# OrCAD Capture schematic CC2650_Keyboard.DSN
size A3; title: CC2650_Keyboard_Module; rev: 2.0.0
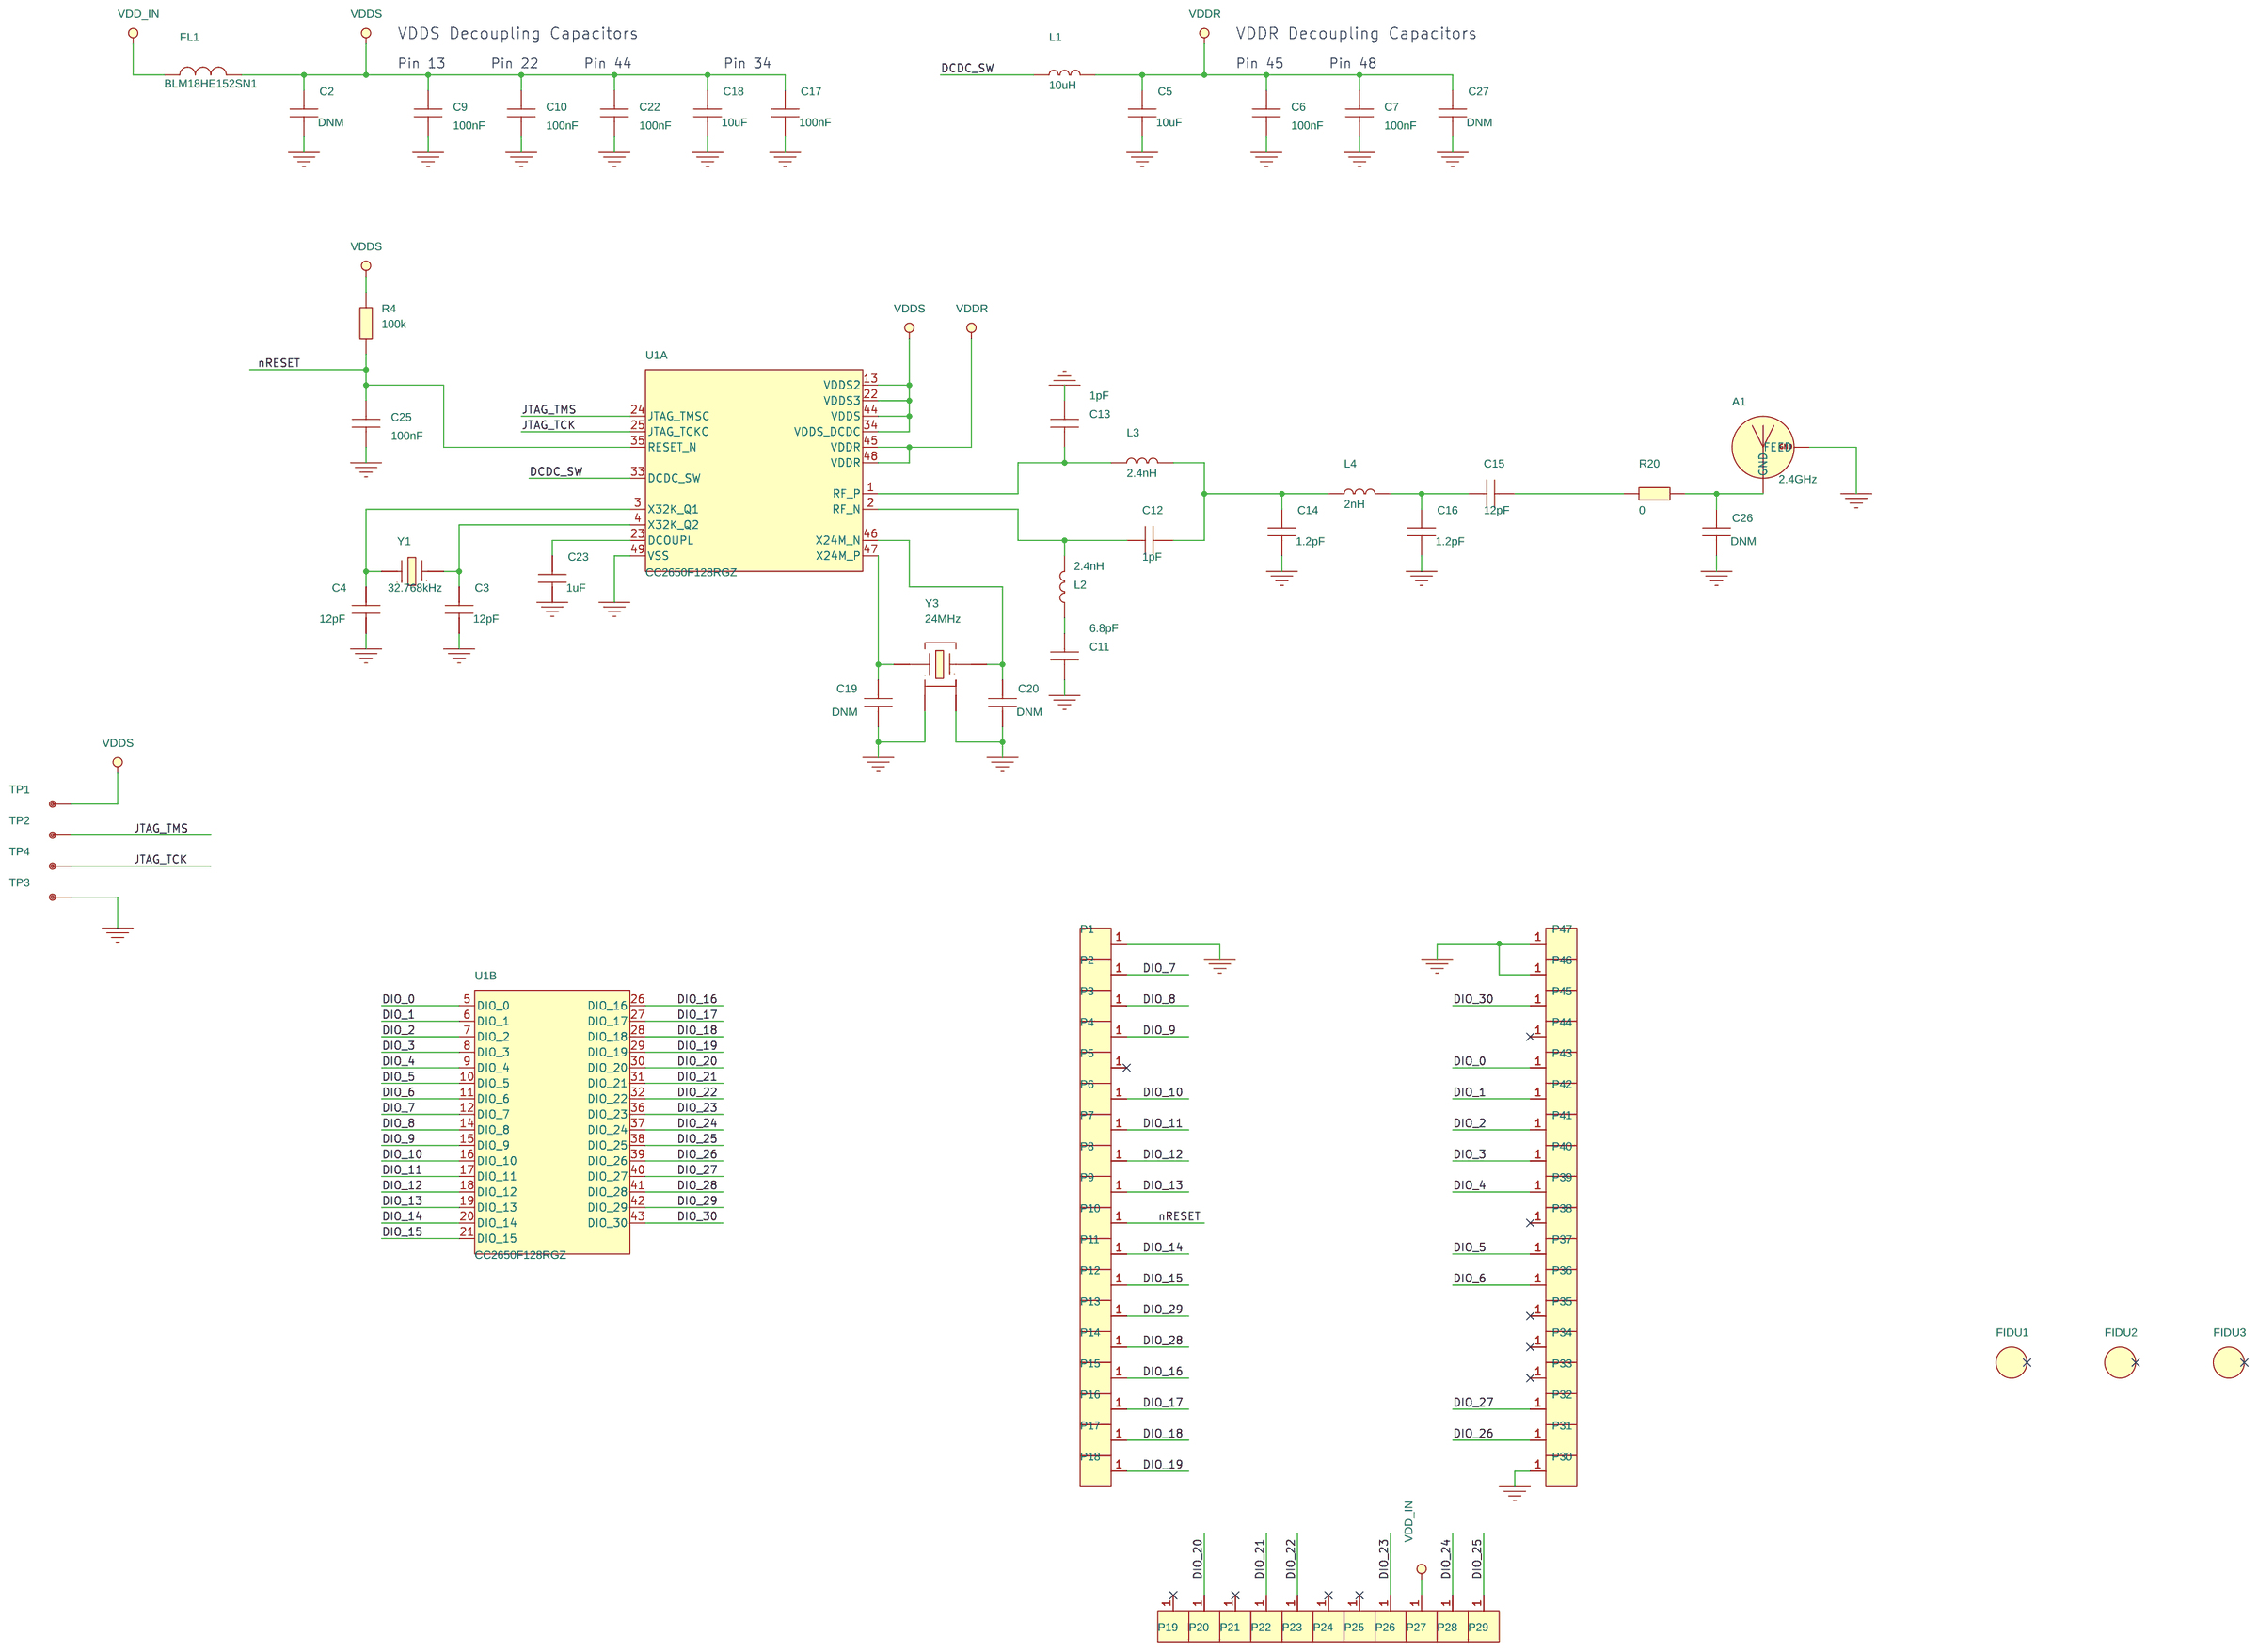
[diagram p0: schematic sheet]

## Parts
A1  2.4GHz  [ANTENNA_MIRROR_AN043CN]
C2  DNM  [CAPC1608X90L]
C3  12pF  [CAPC1005X60L]
C4  12pF  [CAPC1005X60L]
C5  10uF  [CAPC1608X90N]
C6  100nF  [CAPC1005X60L]
C7  100nF  [CAPC1005X60L]
C9  100nF  [CAPC1005X60L]
C10  100nF  [CAPC1005X60L]
C11  6.8pF  [CAPC1005X60L]
C12  1pF  [CAPC1005X60L]
C13  1pF  [CAPC1005X60L]
C14  1.2pF  [CAPC1005X60L]
C15  12pF  [CAPC1005X60L]
C16  1.2pF  [CAPC1005X60L]
C17  100nF  [CAPC1608X90L]
C18  10uF  [CAPC1608X90N]
C19  DNM  [CAPC1005X60L]
C20  DNM  [CAPC1005X60L]
C22  100nF  [CAPC1005X60L]
C23  1uF  [CAPC1005X60L]
C25  100nF  [CAPC1005X60L]
C26  DNM  [CAPC1005X60L]
C27  DNM  [CAPC1005X60L]
FIDU1  FIDU_1MM  [FID100X115]
FIDU2  FIDU_1MM  [FID100X115]
FIDU3  FIDU_1MM  [FID100X115]
FL1  BLM18HE152SN1  [FIL_BLM18HE152SN1DL]
L1  10uH  [INDC2012X150L]
L2  2.4nH  [INDC1005X60L]
L3  2.4nH  [INDC1005X60L]
L4  2nH  [INDC1005X60L]
P1  EDGE PAD  [CON_PAD_500RECT900CIR900]
P2  EDGE PAD  [CON_PAD_500RECT900CIR900]
P3  EDGE PAD  [CON_PAD_500RECT900CIR900]
P4  EDGE PAD  [CON_PAD_500RECT900CIR900]
P5  EDGE PAD  [CON_PAD_500RECT900CIR900]
P6  EDGE PAD  [CON_PAD_500RECT900CIR900]
P7  EDGE PAD  [CON_PAD_500RECT900CIR900]
P8  EDGE PAD  [CON_PAD_500RECT900CIR900]
P9  EDGE PAD  [CON_PAD_500RECT900CIR900]
P10  EDGE PAD  [CON_PAD_500RECT900CIR900]
P11  EDGE PAD  [CON_PAD_500RECT900CIR900]
P12  EDGE PAD  [CON_PAD_500RECT900CIR900]
P13  EDGE PAD  [CON_PAD_500RECT900CIR900]
P14  EDGE PAD  [CON_PAD_500RECT900CIR900]
P15  EDGE PAD  [CON_PAD_500RECT900CIR900]
P16  EDGE PAD  [CON_PAD_500RECT900CIR900]
P17  EDGE PAD  [CON_PAD_500RECT900CIR900]
P18  EDGE PAD  [CON_PAD_500RECT900CIR900]
P19  EDGE PAD  [CON_PAD_500RECT900CIR900]
P20  EDGE PAD  [CON_PAD_500RECT900CIR900]
P21  EDGE PAD  [CON_PAD_500RECT900CIR900]
P22  EDGE PAD  [CON_PAD_500RECT900CIR900]
P23  EDGE PAD  [CON_PAD_500RECT900CIR900]
P24  EDGE PAD  [CON_PAD_500RECT900CIR900]
P25  EDGE PAD  [CON_PAD_500RECT900CIR900]
P26  EDGE PAD  [CON_PAD_500RECT900CIR900]
P27  EDGE PAD  [CON_PAD_500RECT900CIR900]
P28  EDGE PAD  [CON_PAD_500RECT900CIR900]
P29  EDGE PAD  [CON_PAD_500RECT900CIR900]
P30  EDGE PAD  [CON_PAD_500RECT900CIR900]
P31  EDGE PAD  [CON_PAD_500RECT900CIR900]
P32  EDGE PAD  [CON_PAD_500RECT900CIR900]
P33  EDGE PAD  [CON_PAD_500RECT900CIR900]
P34  EDGE PAD  [CON_PAD_500RECT900CIR900]
P35  EDGE PAD  [CON_PAD_500RECT900CIR900]
P36  EDGE PAD  [CON_PAD_500RECT900CIR900]
P37  EDGE PAD  [CON_PAD_500RECT900CIR900]
P38  EDGE PAD  [CON_PAD_500RECT900CIR900]
P39  EDGE PAD  [CON_PAD_500RECT900CIR900]
P40  EDGE PAD  [CON_PAD_500RECT900CIR900]
P41  EDGE PAD  [CON_PAD_500RECT900CIR900]
P42  EDGE PAD  [CON_PAD_500RECT900CIR900]
P43  EDGE PAD  [CON_PAD_500RECT900CIR900]
P44  EDGE PAD  [CON_PAD_500RECT900CIR900]
P45  EDGE PAD  [CON_PAD_500RECT900CIR900]
P46  EDGE PAD  [CON_PAD_500RECT900CIR900]
P47  EDGE PAD  [CON_PAD_500RECT900CIR900]
R4  100k  [RESC1005X40L]
R20  0  [RESC1005X40L]
TP1  TP_1MM_1MM_SMD  [TPS100]
TP2  TP_1MM_1MM_SMD  [TPS100]
TP3  TP_1MM_1MM_SMD  [TPS100]
TP4  TP_1MM_1MM_SMD  [TPS100]
U1  CC2650F128RGZ  [QFNFC50P700X700X80-49CL]  (sections A,B)
Y1  32.768kHz  [XTAL_FC-135N]
Y3  24MHz  [OSCCC250X320X80-4L]

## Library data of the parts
A1 = ANTENNA_AN043: MECHANIC, SMALL SIZE 2.4GHz PCB ANTENNA, SMD; AutoDoc File: http://notefied-dynamic-precision.com/DB/Apps/Desktop/Item/Object.aspx?id=80208; Budget Currency: N/A; Budget Price: N/A; Datasheet URL 1: http://www.ti.com/lit/er/swrz002d/swrz002d.pdf; Datasheet URL 2: http://www.ti.com/lit/ds/symlink/cc2500.pdf; Definied Quality: INDUSTRIAL; Esd Level: HBM 500V; FPLIST: ANTENNA_AN043AN_B,ANTENNA_AN043CN,ANTENNA_AN043AN_B_mirror,ANTENNA_MIRROR_AN043CN,; Last Time Buy: N/A; Lead Time: N/A; MPN: AN043; MPN Status: ACTIVE; MSL: N/A; MTBF: N/A; MTBF Standard: N/A; Manufacturer: TEXAS INSTRUMENTS; Max Oper Temp: +85DEGC; Min Oper Temp: -40DEGC; Mounting Type: SMD; NOTE Status: PREFERRED; Old Footprint: ANTENNA_AN043AN_B,ANTENNA_AN043CN,ANTENNA_AN043AN_B_mirror,ANTENNA_MIRROR_AN043CN; Packing Size: N/A; Packing Type: N/A; Part Number: 13-00290; Part Type: MECHANIC\ANTENNA; Revision: R004; RoHS Status: LEADED; WEIGHT: N/A
C2 = CAPACITOR: CAPACITOR, DO NOT MOUNT, 0603, SMD; ALT_SYMBOLS: CAPC1608X90L,CAPC1608X90M; AutoDoc File: http://notefied-dynamic-precision.com/DB/Apps/Desktop/Item/Object.aspx?id=50475; FPLIST: CAPC1608X90N,CAPC1608X90L,CAPC1608X90M; Old Footprint: CAPC1608X90N,0603; Part Number: 02-01324; Part Type: CAPACITOR\CERAMIC\0603; Revision: R003
C3 C4 = CAPACITOR: CAPACITOR, CERAMIC C0G/NP0, 12pF, 50V, -5%/+5%, -55DEGC/+125DEGC, 0402, SMD; ALT_SYMBOLS: CAPC1005X60L,CAPC1005X60M; AutoDoc File: http://notefied-dynamic-precision.com/DB/Apps/Desktop/Item/Object.aspx?id=80123; Budget Currency: USD; Budget Price: 0.00589; Datasheet URL 1: N/A; Datasheet URL 2: N/A; Definied Quality: INDUSTRIAL; Dielectric Type: C0G/NP0; Esd Level: N/A; FPLIST: CAPC1005X60N,CAPC1005X60L,CAPC1005X60M; Last Time Buy: N/A; Lead Time: N/A; LifeCycle Status: ACTIVE; MPN: CAPACITOR_0402_12pF_C0G/NP0_M_+/-5%_50V; MPN Status: ACTIVE; MSL: N/A; MTBF: N/A; MTBF Standard: N/A; Manufacturer: MANUFACTURER SELECTION; Max Oper Temp: +125DEGC; Max Tol: +5%; Min Oper Temp: -55DEGC; Min Tol: -5%; Mounting Type: SMD; NOTE Status: PREFERRED; Old Footprint: CAPC1005X60N; PCB Package: 0402; Packing Size: 10000; Packing Type: TAPE_&_REEL; Part Number: 02-03030; Part Type: CAPACITOR\CERAMIC\0402; Revision: R000; RoHS Status: ROHS_COMPLIANT; Rtd Voltage: 50V; WEIGHT: N/A
C5 C18 = CAPACITOR: CAPACITOR, CERAMIC X5R, 10uF, 6.3V, -20%/+20%, -55DEGC/+85DEGC, 0603, SMD; ALT_SYMBOLS: CAPC1608X90L,CAPC1608X90M; AutoDoc File: http://notefied-dynamic-precision.com/DB/Apps/Desktop/Item/Object.aspx?id=74686; Budget Currency: EUR; Budget Price: 0.067; Datasheet URL 1: http://search.murata.co.jp/Ceramy/image/img/w_hinm/L0005E.pdf; Datasheet URL 2: http://psearch.murata.com/capacitor/product/GRM188R60J106ME47%23.pdf; Definied Quality: INDUSTRIAL; Dielectric Type: X5R; Esd Level: N/A; FPLIST: CAPC1608X90N,CAPC1608X90L,CAPC1608X90M; Last Time Buy: N/A; Lead Time: 20; MPN: GRM188R60J106ME47D; MPN Status: NRND; MSL: 1; MTBF: N/A; MTBF Standard: N/A; Manufacturer: MURATA; Max Oper Temp: +85DEGC; Max Tol: +20%; Min Oper Temp: -55DEGC; Min Tol: -20%; Mounting Type: SMD; NOTE Status: PREFERRED; PCB Package: 0603; Packing Size: 4000; Packing Type: TAPE_&_REEL; Part Number: 02-02419; Part Type: CAPACITOR\CERAMIC\0603; Revision: R003; RoHS Status: ROHS_COMPLIANT; Rtd Voltage: 6.3V; WEIGHT: 0.0063g
C6 C7 C9 C10 C22 C25 = CAPACITOR: CAPACITOR, CERAMIC X7R, 100nF, 6.3V, -10%/+10%, -55DEGC/+125DEGC, 0402, SMD; ALT_SYMBOLS: CAPC1005X60L,CAPC1005X60M; AutoDoc File: http://notefied-dynamic-precision.com/DB/Apps/Desktop/Item/Object.aspx?id=73748; Budget Currency: EUR; Budget Price: 0.003; Datasheet URL 1: http://search.murata.co.jp/Ceramy/image/img/A01X/G101/ENG/GRM155R70J104KA01-01.pdf; Datasheet URL 2: http://search.murata.co.jp/Ceramy/image/img/A01X/G101/ENG/GRM155R70J104KA01-01.pdf; Dielectric Type: X7R; FPLIST: CAPC1005X60N,CAPC1005X60L,CAPC1005X60M; Lead Time: 10; LifeCycle Status: ACTIVE; MPN: GRM155R70J104KA01D; MPN Status: ACTIVE; Manufacturer: MURATA; Max Oper Temp: +125DEGC; Max Tol: +10%; Min Oper Temp: -55DEGC; Min Tol: -10%; Mounting Type: SMD; NOTE Status: PREFERRED; Old Footprint: CAPC1005X60N,0402; PCB Package: 0402; Packing Size: 10000; Packing Type: TAPE_&_REEL; Part Number: 02-02323; Part Type: CAPACITOR\CERAMIC\0402; Revision: R000; RoHS Status: ROHS_COMPLIANT; Rtd Voltage: 6.3V; WEIGHT: 0.0016g
C11 = CAPACITOR: CAPACITOR, CERAMIC C0G/NP0, 6.8pF, 50V, -0.25pF, +0.25pF, -55DEGC/+125DEGC, 0402, SMD; ALT_SYMBOLS: CAPC1005X60L,CAPC1005X60M; AutoDoc File: http://notefied-dynamic-precision.com/DB/Apps/Desktop/Item/Object.aspx?id=84868; Budget Currency: EUR; Budget Price: 0.004; Datasheet URL 1: http://search.murata.co.jp/Ceramy/image/img/A01X/G101/ENG/GRM1555C1H6R8CA01-01.pdf; Datasheet URL 2: http://search.murata.co.jp/Ceramy/image/img/A01X/G101/ENG/GRM1555C1H6R8CA01-01.pdf; Dielectric Type: C0G/NP0; FPLIST: CAPC1005X60N,CAPC1005X60L,CAPC1005X60M; Lead Time: 12; MPN: GRM1555C1H6R8CA01D; MPN Status: ACTIVE; Manufacturer: MURATA; Max Oper Temp: +125DEGC; Max TC: +30PPM/DEGC; Max Tol: +0.25pF; Min Oper Temp: -55DEGC; Min TC: -30PPM/DEGC; Min Tol: -0.25pF; Mounting Type: SMD; NOTE Status: PREFERRED; Old Footprint: CAPC1005X60N; PCB Package: 0402; Packing Size: 10000; Packing Type: TAPE_&_REEL; Part Number: 02-04169; Part Type: CAPACITOR\CERAMIC\0402; Revision: R000; RoHS Status: ROHS_COMPLIANT; Rtd Voltage: 50V; WEIGHT: 0.0016g
C12 C13 = CAPACITOR: CAPACITOR, CERAMIC C0G/NP0, 1pF, 50V, -0.25pF/ +0.25pF, -55DEGC/+125DEGC, 0402, SMD; ALT_SYMBOLS: CAPC1005X60L,CAPC1005X60M; AutoDoc File: http://notefied-dynamic-precision.com/DB/Apps/Desktop/Item/Object.aspx?id=87790; Budget Currency: EUR; Budget Price: 0.003; Datasheet URL 2: http://psearch.murata.com/capacitor/product/GRM1555C1H1R0CA01%23.pdf; Dielectric Type: C0G/NP0; FPLIST: CAPC1005X60N,CAPC1005X60L,CAPC1005X60M; Lead Time: 12; MPN: GRM1555C1H1R0CA01D; MPN Status: ACTIVE; Manufacturer: MURATA; Max Oper Temp: +125DEGC; Max TC: +30PPM/DEGC; Max Tol: +0.25pF; Min Oper Temp: -55DEGC; Min TC: -30PPM/DEGC; Min Tol: -0.25pF; Mounting Type: SMD; NOTE Status: PREFERRED; Old Footprint: CAPC1005X60N; PCB Package: 0402; Packing Size: 10000; Packing Type: TAPE_&_REEL; Part Number: 02-04672; Part Type: CAPACITOR\CERAMIC\0402; Revision: R001; RoHS Status: ROHS_COMPLIANT; Rtd Voltage: 50V; WEIGHT: 1.6mg
C14 C16 = CAPACITOR: CAPACITOR, CERAMIC C0G/NP0, 1.2pF, 50V, -0.1pF/ +0.1pF, -55DEGC/+125DEGC, 0402, SMD; ALT_SYMBOLS: CAPC1005X60L,CAPC1005X60M; AutoDoc File: http://notefied-dynamic-precision.com/DB/Apps/Desktop/Item/Object.aspx?id=87789; Budget Currency: EUR; Budget Price: 0.006; Datasheet URL 1: http://search.murata.co.jp/Ceramy/image/img/w_hinm/L0005E.pdf; Datasheet URL 2: http://psearch.murata.com/capacitor/product/GRM1555C1H1R2BA01%23.pdf; Definied Quality: INDUSTRIAL; Dielectric Type: C0G/NP0; Esd Level: N/A; FPLIST: CAPC1005X60N,CAPC1005X60L,CAPC1005X60M; Last Time Buy: N/A; Lead Time: 12; MPN: GRM1555C1H1R2BA01D; MPN Status: ACTIVE; MSL: 1; MTBF: N/A; MTBF Standard: N/A; Manufacturer: MURATA; Max Oper Temp: +125DEGC; Max TC: +30PPM/DEGC; Max Tol: +0.1pF; Min Oper Temp: -55DEGC; Min TC: -30PPM/DEGC; Min Tol: -0.1pF; Mounting Type: SMD; NOTE Status: PREFERRED; Old Footprint: CAPC1005X60N; PCB Package: 0402; Packing Size: 10000; Packing Type: TAPE_&_REEL; Part Number: 02-04671; Part Type: CAPACITOR\CERAMIC\0402; Revision: R001; RoHS Status: ROHS_COMPLIANT; Rtd Voltage: 50V; WEIGHT: 0.0016g
C15 = CAPACITOR: CAPACITOR, CERAMIC C0G/NP0, 12pF, 50V, -5%/+5%, -55DEGC/+125DEGC, 0402, SMD; ALT_SYMBOLS: CAPC1005X60L,CAPC1005X60M; AutoDoc File: http://notefied-dynamic-precision.com/DB/Apps/Desktop/Item/Object.aspx?id=84867; Budget Currency: EUR; Budget Price: 0.004; Datasheet URL 1: http://search.murata.co.jp/Ceramy/image/img/A01X/G101/ENG/GRM1555C1H120JA01-01.pdf; Datasheet URL 2: http://search.murata.co.jp/Ceramy/image/img/A01X/G101/ENG/GRM1555C1H120JA01-01.pdf; Dielectric Type: C0G/NP0; FPLIST: CAPC1005X60N,CAPC1005X60L,CAPC1005X60M; Lead Time: 12; MPN: GRM1555C1H120JA01D; MPN Status: ACTIVE; Manufacturer: MURATA; Max Oper Temp: +125DEGC; Max TC: +30PPM/DEGC; Max Tol: +5%; Min Oper Temp: -55DEGC; Min TC: -30PPM/DEGC; Min Tol: -5%; Mounting Type: SMD; NOTE Status: PREFERRED; Old Footprint: CAPC1005X60N; PCB Package: 0402; Packing Size: 10000; Packing Type: TAPE_&_REEL; Part Number: 02-04168; Part Type: CAPACITOR\CERAMIC\0402; Revision: R000; RoHS Status: ROHS_COMPLIANT; Rtd Voltage: 50V; WEIGHT: 0.0016g
C17 = CAPACITOR: CAPACITOR, CERAMIC X7R, 100nF, 25V, -10%/+10%, -55DEGC/+125DEGC, 0603, SMD; ALT_SYMBOLS: CAPC1608X90L,CAPC1608X90M; AutoDoc File: http://notefied-dynamic-precision.com/DB/Apps/Desktop/Item/Object.aspx?id=72070; Budget Currency: N/A; Budget Price: 0.00391; Cage Code: C0151; Datasheet URL 1: http://search.murata.co.jp/Ceramy/image/img/A01X/G101/ENG/GRM188R71E104KA01-01.pdf; Datasheet URL 2: http://search.murata.co.jp/Ceramy/image/img/A01X/G101/ENG/GRM188R71E104KA01-01.pdf; Dielectric Type: X7R; FPLIST: CAPC1608X90N,CAPC1608X90L,CAPC1608X90M; MPN: GRM188R71E104KA01D; MPN Status: ACTIVE; Manufacturer: MURATA; Max Oper Temp: +125DEGC; Max Tol: +10%; Min Oper Temp: -55DEGC; Min Tol: -10%; Mounting Type: SMD; NOTE Status: PREFERRED; Old Footprint: CAPC1608X90N,0603; PCB Package: 0603; Packing Size: 4000; Packing Type: TAPE_&_REEL; Part Number: 02-01992; Part Type: CAPACITOR\CERAMIC\0603; Revision: R000; RoHS Status: ROHS_COMPLIANT; Rtd Voltage: 25V; WEIGHT: 0.0063g
C19 C20 C26 C27 = CAPACITOR: CAPACITOR, CERAMIC, N/A VALUE, -55DEGC/+125DEGC, 0402, SMD; ALT_SYMBOLS: CAPC1005X60L,CAPC1005X60M; AutoDoc File: http://notefied-dynamic-precision.com/DB/Apps/Desktop/Item/Object.aspx?id=84862; Budget Currency: USD; Budget Price: 0.00589; FPLIST: CAPC1005X60N,CAPC1005X60L,CAPC1005X60M; MPN: CAPACITOR_0402_DNM_N/A_M; MPN Status: ACTIVE; Manufacturer: Manufacturer selection; Max Oper Temp: +125DEGC; Min Oper Temp: -55DEGC; Mounting Type: SMD; NOTE Status: PREFERRED; Old Footprint: CAPC1005X60N; PCB Package: 0402; Packing Size: 10000; Packing Type: TAPE_&_REEL; Part Number: 02-04164; Part Type: CAPACITOR\CERAMIC\0402; Revision: R000; RoHS Status: PART NOT KNOWN
C23 = CAPACITOR: CAPACITOR, CERAMIC, 1uF, -20%+80%, Y5V, 6.3V, 0402, SMD; ALT_SYMBOLS: CAPC1005X60L,CAPC1005X60M; AutoDoc File: http://notefied-dynamic-precision.com/DB/Apps/Desktop/Item/Object.aspx?id=49715; Budget Currency: EUR; Budget Price: 0.013; Datasheet URL 1: http://search.murata.co.jp/Ceramy/image/img/A01X/G101/ENG/GRM155F50J105ZE01-01.pdf; Datasheet URL 2: http://search.murata.co.jp/Ceramy/image/img/A01X/G101/ENG/GRM155F50J105ZE01-01.pdf; Dielectric Type: Y5V; FPLIST: CAPC1005X60N,CAPC1005X60L,CAPC1005X60M; Lead Time: 10; LifeCycle Status: GROWTH; MPN: GRM155F50J105ZE01D; MPN Status: ACTIVE; Manufacturer: MURATA; Max Oper Temp: +125DEGC; Min Oper Temp: -55DEGC; Min Tol: -20%; Mounting Type: SMD; NOTE Status: PREFERRED; Old Footprint: CAPC1005X60N,0402; PCB Package: 0402; Packing Size: 10000; Packing Type: TAPE_&_REEL; Part Number: 02-00564; Part Type: CAPACITOR\CERAMIC\0402; Revision: R001; RoHS Status: ROHS_COMPLIANT; Rtd Voltage: 6.3V; WEIGHT: 0.0016g
FIDU1-FIDU3 = FIDMARK: FIDUCIAL MARK, ROUND 1MM; AutoDoc File: https://notefied-dynamic-precision.com/NotefiedWebServices/AutoDocs.aspx?itemid=74548; Part Number: 19-00111; Part Type: NON_COMPONENT\FIDUCIAL; Revision: R001
FL1 = FILTER_2PIN: FILTER, EMI, 1500@100MHz, -55DEGC/+125DEGC, 0603, SMD; ALT_SYMBOLS: FIL_BLM18HE152SN1DL,FIL_BLM18HE152SN1DM; AutoDoc File: http://notefied-dynamic-precision.com/DB/Apps/Desktop/Item/Object.aspx?id=85575; Budget Currency: EUR; Budget Price: 0.085; Datasheet URL 1: http://search.murata.co.jp/Ceramy/image/img/PDF/ENG/L0110S0101BLM18H.pdf; Datasheet URL 2: http://search.murata.co.jp/Ceramy/image/img/PDF/ENG/L0110S0101BLM18H.pdf; FPLIST: FIL_BLM18HE152SN1DN,FIL_BLM18HE152SN1DL,FIL_BLM18HE152SN1DM; Impedance: 1500@100MHz; Lead Time: 26; MPN: BLM18HE152SN1D; MPN Status: ACTIVE; Manufacturer: MURATA; Max Oper Temp: +125DEGC; Max Tol: +25%; Min Oper Temp: -55DEGC; Min Tol: -25%; Mounting Type: SMD; NOTE Status: PREFERRED; Old Footprint: FIL_BLM18HE152SN1DN; PCB Package: 0603; Packing Size: 4000; Packing Type: TAPE_&_REEL; Part Number: 04-00470; Part Type: FILTER\EMI\0603; Revision: R001; RoHS Status: ROHS_COMPLIANT; Rtd Current: 0.5A; WEIGHT: 0.006g
L1 = INDUCTOR: INDUCTOR, CHIP, 10uH, -20%/+20%, 0.11A, -40DEGC/+85DEGC, 0805, SMD; ALT_SYMBOLS: INDC2012X150L,INDC2012X150M; AutoDoc File: http://notefied-dynamic-precision.com/DB/Apps/Desktop/Item/Object.aspx?id=84960; Budget Currency: USD; Budget Price: 0.04; Datasheet URL 1: http://www.yuden.co.jp/us/product/pdf/mlci_all_e.pdf; Datasheet URL 2: http://www.yuden.co.jp/us/product/pdf/mlci_all_e.pdf; FPLIST: INDC2012X150N,INDC2012X150L,INDC2012X150M; Frequency: 24MHz; MPN: CKS2125100M-T; MPN Status: ACTIVE; Manufacturer: TAIYO YUDEN; Max Oper Temp: +85DEGC; Max Tol: +20%; Min Oper Temp: -40DEGC; Min Tol: -20%; Mounting Type: SMD; NOTE Status: PREFERRED; Old Footprint: INDC2012X150N; PCB Package: 0805; Packing Size: 4000; Packing Type: TAPE_&_REEL; Part Number: 03-06514; Part Type: INDUCTOR\CHIP\0805; Revision: R001; RoHS Status: ROHS_COMPLIANT; Rtd Current: 0.11A
L2 L3 = INDUCTOR: INDUCTOR, CHIP, 2.4nH, -0.3nH/+0.3nH, 0.3A, -55DEGC/+125DEGC, 0402, SMD; ALT_SYMBOLS: INDC1005X60M,INDC1005X60L; AutoDoc File: http://notefied-dynamic-precision.com/DB/Apps/Desktop/Item/Object.aspx?id=86086; Budget Currency: EUR; Budget Price: 0.021; Datasheet URL 1: http://search.murata.co.jp/Ceramy/image/img/PDF/ENG/L0075S0083LQG15HN.pdf; Datasheet URL 2: http://search.murata.co.jp/Ceramy/image/img/PDF/ENG/L0075S0083LQG15HN.pdf; FPLIST: INDC1005X60N,INDC1005X60M,INDC1005X60L; Frequency: 6GHz; Lead Time: 7; MPN: LQG15HN2N4S02D; MPN Status: ACTIVE; Manufacturer: MURATA; Max Oper Temp: +125DEGC; Max Tol: +0.3nH; Min Oper Temp: -55DEGC; Min Tol: -0.3nH; Mounting Type: SMD; NOTE Status: PREFERRED; Old Footprint: INDC1005X60N; PCB Package: 0402; Packing Size: 10000; Packing Type: TAPE_&_REEL; Part Number: 03-06554; Part Type: INDUCTOR\CHIP\0402; Resistance: 0.16; Revision: R001; RoHS Status: ROHS_COMPLIANT; Rtd Current: 0.3A; WEIGHT: 0.001g
L4 = INDUCTOR: INDUCTOR, CHIP, 2nH, -0.3nH/ +0.3nH, 0.3A, -55DEGC/+125DEGC, 0402, SMD; ALT_SYMBOLS: INDC1005X60L,INDC1005X60M; AutoDoc File: http://notefied-dynamic-precision.com/DB/Apps/Desktop/Item/Object.aspx?id=85431; Budget Currency: EUR; Budget Price: 0.021; Datasheet URL 1: http://search.murata.co.jp/Ceramy/image/img/PDF/ENG/L0075S0083LQG15HS.pdf; Datasheet URL 2: http://search.murata.co.jp/Ceramy/image/img/PDF/ENG/L0075S0083LQG15HS.pdf; FPLIST: INDC1005X60N,INDC1005X60L,INDC1005X60M; Frequency: 6GHz; Lead Time: 9; MPN: LQG15HS2N0S02D; MPN Status: ACTIVE; Manufacturer: MURATA; Max Oper Temp: +125DEGC; Max Tol: +0.3nH; Min Oper Temp: -55DEGC; Min Tol: -0.3nH; Mounting Type: SMD; NOTE Status: PREFERRED; Old Footprint: INDC1005X60N; PCB Package: 0402; Packing Size: 10000; Packing Type: TAPE_&_REEL; Part Number: 03-06525; Part Type: INDUCTOR\CHIP\0402; Revision: R001; RoHS Status: ROHS_COMPLIANT; Rtd Current: 0.3A; WEIGHT: 0.001g
P1-P47 = PAD: NON COMPONENT, PAD, PAD 900 500X900; AutoDoc File: https://notefied-dynamic-precision.com/NotefiedWebServices/AutoDocs.aspx?itemid=90721; FPLIST: CON_PAD_500RECT900CIR900,; Part Number: 19-00411; Part Type: NON_COMPONENT\PAD; Revision: R001
R4 = RESISTOR: RESISTOR, THICK FILM, 100k, -1%/+1%, 0.063W, 50V, -55DEGC/+155DEGC, 0402, SMD; ALT_SYMBOLS: RESC1005X40L,RESC1005X40M; AutoDoc File: http://notefied-dynamic-precision.com/DB/Apps/Desktop/Item/Object.aspx?id=76892; Budget Currency: USD; Budget Price: 0.00244; Datasheet URL 1: N/A; Datasheet URL 2: N/A; Definied Quality: INDUSTRIAL; Esd Level: N/A; FPLIST: RESC1005X40N,RESC1005X40L,RESC1005X40M; Last Time Buy: N/A; Lead Time: N/A; LifeCycle Status: ACTIVE; MPN: RESISTOR_0402_100k_+/-1%_50V_0.063W_M_+/-100PPM; MPN Status: ACTIVE; MSL: N/A; MTBF: N/A; MTBF Standard: N/A; Manufacturer: MANUFACTURER SELECTION; Max Oper Temp: +155DEGC; Max TC: +100PPM/DEGC; Max Tol: +1%; Min Oper Temp: -55DEGC; Min TC: -100PPM/DEGC; Min Tol: -1%; Mounting Type: SMD; NOTE Status: PREFERRED; Old Footprint: RESC1005X40N; PCB Package: 0402; Packing Size: 10000; Packing Type: TAPE_&_REEL; Part Number: 01-12837; Part Type: RESISTOR\0402\PRECISION; Resistor Type: THICK FILM; Revision: R002; RoHS Status: ROHS_COMPLIANT; Rtd Power: 0.063W; Rtd Voltage: 50V; WEIGHT: N/A
R20 = RESISTOR: RESISTOR, JUMPER, -55DEGC/+155DEGC, 0402, SMD; ALT_SYMBOLS: RESC1005X40L,RESC1005X40M; AutoDoc File: http://notefied-dynamic-precision.com/DB/Apps/Desktop/Item/Object.aspx?id=47668; Budget Currency: EUR; Budget Price: 0.016; Datasheet URL 1: http://www.koaspeer.com/pdfs/Appendix_A.pdf; Datasheet URL 2: http://www.koaspeer.com/catimages/Products/RK73Z/RK73Z.pdf; Definied Quality: INDUSTRIAL; Esd Level: N/A; FPLIST: RESC1005X40N,RESC1005X40L,RESC1005X40M; Last Time Buy: N/A; Lead Time: 10; LifeCycle Status: ACTIVE; MPN: RK73Z1ETTP; MPN Status: ACTIVE; MSL: 1; MTBF: N/A; MTBF Standard: N/A; Manufacturer: KOA SPEER; Max Oper Temp: +155DEGC; Min Oper Temp: -55DEGC; Mounting Type: SMD; NOTE Status: PREFERRED; Old Footprint: RESC1005X40N,0402; PCB Package: 0402; Packing Size: 10000; Packing Type: TAPE_&_REEL; Part Number: 01-01784; Part Type: RESISTOR\JUMPER\0402; Revision: R002; RoHS Status: ROHS_COMPLIANT; Rtd Current: 1A; WEIGHT: 0.00068g
TP1-TP4 = TEST_POINT: NON COMPONENT, TESTPOINT, 1MM X 1MM, SMD; AutoDoc File: https://notefied-dynamic-precision.com/NotefiedWebServices/AutoDocs.aspx?itemid=87032; FPLIST: TPS100,; Part Number: 19-00317; Part Type: NON_COMPONENT\TEST_POINT; Revision: R001
U1 = IC_RF_CC26XX_QFN48_V2: IC, DIGITAL, 2.4GHZ SIMPLELINK WIRELESS MCU, PITCH 0,5MM, QFN48, SMD; ALT_SYMBOLS: QFNFC50P700X700X80-49CL,QFNFC50P700X700X80-49CM; AutoDoc File: http://notefied-dynamic-precision.com/DB/Apps/Desktop/Item/Object.aspx?id=88778; Budget Currency: N/A; Budget Price: N/A; Datasheet URL 1: N/A; Datasheet URL 2: www.ti.com; Definied Quality: COMMERCIAL; Esd Level: N/A; FPLIST: QFNFC50P700X700X80-49CN,QFNFC50P700X700X80-49CL,QFNFC50P700X700X80-49CM; Last Time Buy: N/A; Lead Time: N/A; MPN: CC2650F128RGZT; MPN Status: PRELIMINARY; MSL: N/A; MTBF: N/A; MTBF Standard: N/A; Manufacturer: TEXAS INSTRUMENTS; Max Oper Temp: +85DEGC; Min Oper Temp: -40DEGC; Mounting Type: SMD; NOTE Status: PREFERRED; Old Footprint: QFNFC50P700X700X80-49CN; PCB Package: QFN48; Packing Size: 2500; Packing Type: TAPE_&_REEL; Part Number: 18-28499; Part Type: IC\DIGITAL\WIRELESS; Revision: R003; RoHS Status: ROHS_COMPLIANT; Rtd Voltage: 3.8V; WEIGHT: N/A
Y1 = CRYSTAL: CRYSTAL, RESONATOR, 32.768kHz, -20PPM/+20PPM, -40DEGC/+85DEGC, SMD; ALT_SYMBOLS: XTAL_FC-135L,XTAL_FC-135M; AutoDoc File: http://notefied-dynamic-precision.com/DB/Apps/Desktop/Item/Object.aspx?id=91966; Budget Currency: USD; Budget Price: 1.25375; Capacitance: 7pF; Datasheet URL 1: http://www.eea.epson.com/portal/pls/portal/docs/1/1525528.PDF; Datasheet URL 2: http://www.eea.epson.com/portal/pls/portal/docs/1/1525451.PDF; Definied Quality: INDUSTRIAL; Esd Level: N/A; FPLIST: XTAL_FC-135N,XTAL_FC-135L,XTAL_FC-135M; Last Time Buy: N/A; Lead Time: 10; MPN: FC-135 32.7680KA-AG0; MPN Status: ACTIVE; MSL: N/A; MTBF: N/A; MTBF Standard: N/A; Manufacturer: EPSON; Max Oper Temp: +85DEGC; Max Tol: +20PPM; Min Oper Temp: -40DEGC; Min Tol: -20PPM; Mounting Type: SMD; NOTE Status: PREFERRED; Packing Size: 1000; Packing Type: TAPE_&_REEL; Part Number: 12-00546; Part Type: CRYSTAL\OSCILLATOR\MEMS; Revision: R001; RoHS Status: ROHS_COMPLIANT; WEIGHT: N/A
Y3 = XTAL_TSX_3225_V1: CRYSTAL, OSCILATOR, 24MHz, -40DEGC/+85DEGC, SMD; ALT_SYMBOLS: OSCCC250X320X80-4L,OSCCC250X320X80-4M; AutoDoc File: http://notefied-dynamic-precision.com/DB/Apps/Desktop/Item/Object.aspx?id=85182; Capacitance: 7pF; Datasheet URL 1: http://ndap3-net.ebz.epson.co.jp/w/www/PDFS/epdoc_qd.nsf/85a4e2c523a1f89349257068002f9e30/31e98956c8f991cd4925707c003b38b1/$FILE/FA-238_238V_TSX-3225_E09X.pdf; Datasheet URL 2: http://ndap3-net.ebz.epson.co.jp/w/www/PDFS/epdoc_qd.nsf/85a4e2c523a1f89349257068002f9e30/31e98956c8f991cd4925707c003b38b1/$FILE/FA-238_238V_TSX-3225_E09X.pdf; FPLIST: OSCCC250X320X80-4N,OSCCC250X320X80-4L,OSCCC250X320X80-4M; MPN: TSX-3225 24MHz; MPN Status: ACTIVE; Manufacturer: Epson Toyocom; Max Oper Temp: +85DEGC; Min Oper Temp: -40DEGC; Mounting Type: SMD; NOTE Status: PREFERRED; Old Footprint: OSCCC250X320X80-4N; Part Number: 12-00419; Part Type: CRYSTAL\OSCILLATOR; Revision: R001; RoHS Status: ROHS_COMPLIANT

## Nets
GND: A1.2(FEED) C2.2 C3.2 C4.2 C5.2 C6.2 C7.2 C9.2 C10.2 C11.2 C13.1 C14.2 C16.2 C17.2 C18.2 C19.2 C20.2 C22.2 C23.2 C25.2 C26.2 C27.2 P1.1 P30.1 P46.1 P47.1 TP3.1 U1.49(VSS) Y3.2 Y3.4
VDD_IN: FL1.2 P27.1
VDDR: C5.1 C6.1 C7.1 C27.1 L1.2 U1.45(VDDR) U1.48(VDDR)
VDDS: C2.1 C9.1 C10.1 C17.1 C18.1 C22.1 FL1.1 R4.2 TP1.1 U1.13(VDDS2) U1.22(VDDS3) U1.34(VDDS_DCDC) U1.44(VDDS)
DCDC_SW: L1.1 U1.33(DCDC_SW)
DIO_0: P43.1 U1.5(DIO_0)
DIO_1: P42.1 U1.6(DIO_1)
DIO_2: P41.1 U1.7(DIO_2)
DIO_3: P40.1 U1.8(DIO_3)
DIO_4: P39.1 U1.9(DIO_4)
DIO_5: P37.1 U1.10(DIO_5)
DIO_6: P36.1 U1.11(DIO_6)
DIO_7: P2.1 U1.12(DIO_7)
DIO_8: P3.1 U1.14(DIO_8)
DIO_9: P4.1 U1.15(DIO_9)
DIO_10: P6.1 U1.16(DIO_10)
DIO_11: P7.1 U1.17(DIO_11)
DIO_12: P8.1 U1.18(DIO_12)
DIO_13: P9.1 U1.19(DIO_13)
DIO_14: P11.1 U1.20(DIO_14)
DIO_15: P12.1 U1.21(DIO_15)
DIO_16: P15.1 U1.26(DIO_16)
DIO_17: P16.1 U1.27(DIO_17)
DIO_18: P17.1 U1.28(DIO_18)
DIO_19: P18.1 U1.29(DIO_19)
DIO_20: P20.1 U1.30(DIO_20)
DIO_21: P22.1 U1.31(DIO_21)
DIO_22: P23.1 U1.32(DIO_22)
DIO_23: P26.1 U1.36(DIO_23)
DIO_24: P28.1 U1.37(DIO_24)
DIO_25: P29.1 U1.38(DIO_25)
DIO_26: P31.1 U1.39(DIO_26)
DIO_27: P32.1 U1.40(DIO_27)
DIO_28: P14.1 U1.41(DIO_28)
DIO_29: P13.1 U1.42(DIO_29)
DIO_30: P45.1 U1.43(DIO_30)
JTAG_TCK: TP4.1 U1.25(JTAG_TCKC)
JTAG_TMS: TP2.1 U1.24(JTAG_TMSC)
nRESET: C25.1 P10.1 R4.1 U1.35(RESET_N)
N310466: C19.1 U1.47(X24M_P) Y3.1
N310868: C20.1 U1.46(X24M_N) Y3.3
N314432: C12.1 L2.1 U1.2(RF_N)
N314470: C13.2 L3.1 U1.1(RF_P)
N314764: C12.2 C14.1 L3.2 L4.1
N315193: C15.1 C16.1 L4.2
N315257: C15.2 R20.2
N316022: A1.1(GND) C26.1 R20.1
N316649: C23.1 U1.23(DCOUPL)
N316932: C3.1 U1.4(X32K_Q2) Y1.2
N361373: C11.1 L2.2
N620376: C4.1 U1.3(X32K_Q1) Y1.1

Not connected (* = marked no-connect by the designer): FIDU1 1*; FIDU2 1*; FIDU3 1*; P5 1*; P19 1*; P21 1*; P24 1*; P25 1*; P33 1*; P34 1*; P35 1*; P38 1*; P44 1*

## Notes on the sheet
- VDDS Decoupling Capacitors
- VDDR Decoupling Capacitors
- Pin 13
- Pin 22
- Pin 44
- Pin 34
- Pin 45
- Pin 48
